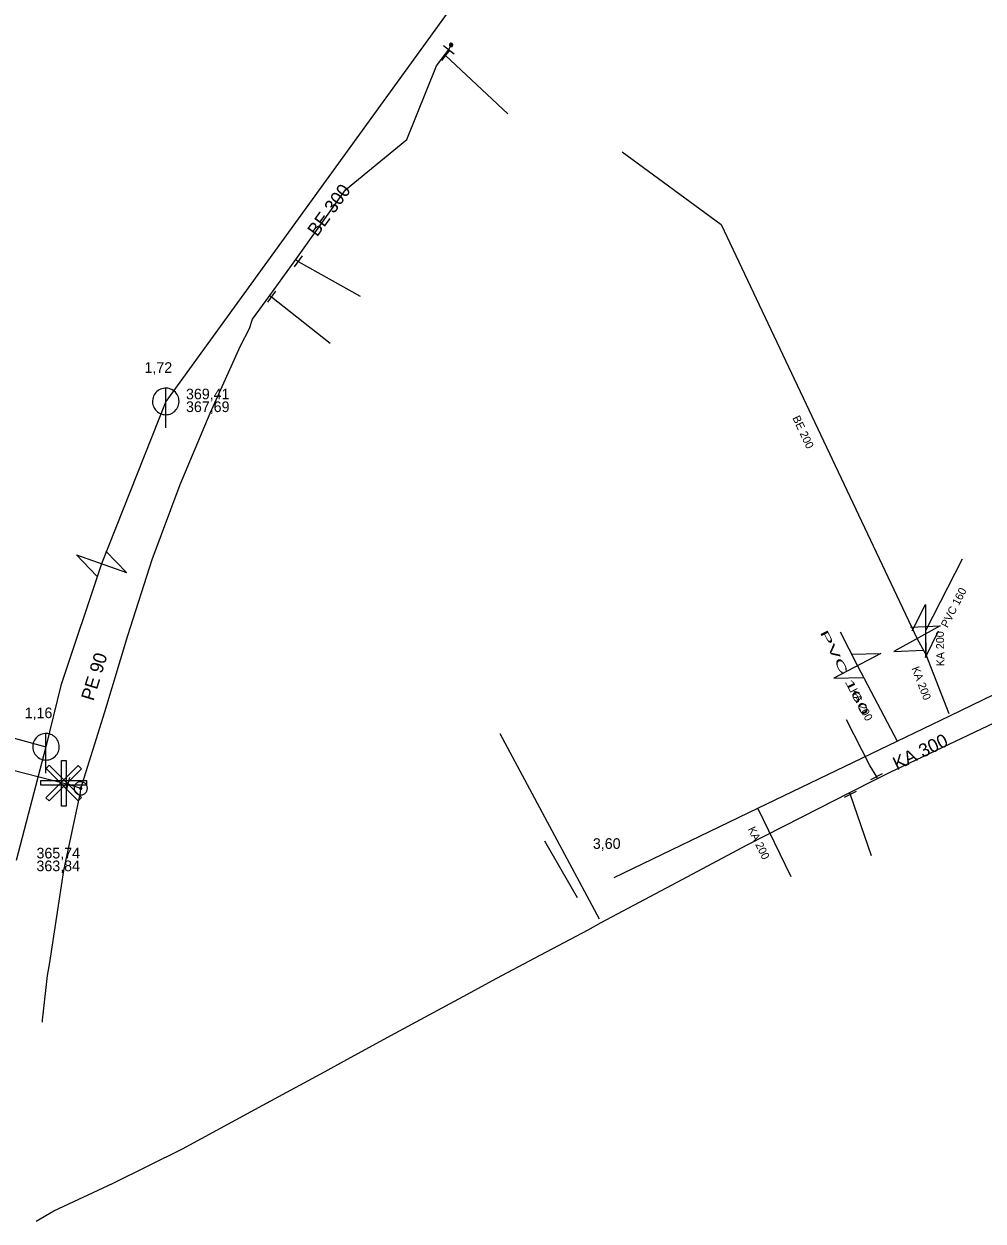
# Model space of a CAD drawing. Extents: x -809028 to -807737, y -990545 to -989489.
# Drawn here: x -808817.2 to -808745.1, y -990286.3 to -990196.1 of the extents above; entities that cross this region are included whole.
import ezdxf

# ---------------------------------------------------------------- set-up
doc = ezdxf.new("R2010")
doc.units = 0
doc.header["$LTSCALE"] = 0.32
for name, color, linetype, lineweight in [('1', 7, 'Continuous', 13), ('11', 7, 'Continuous', 13), ('12', 7, 'Continuous', 13), ('13', 7, 'Continuous', 13), ('14', 7, 'Continuous', 25), ('17', 7, 'Continuous', 25), ('22', 7, 'Continuous', 13), ('31', 7, 'Continuous', 13), ('34', 7, 'Continuous', 13), ('47', 7, 'Continuous', 13), ('9', 7, 'Continuous', 13)]:
    doc.layers.add(name, color=color, linetype=linetype, lineweight=lineweight)

msp = doc.modelspace()

# ---------------------------------------------------------------- linework, layer by layer
at = {"layer": '11'}
for p, q in [((-808746.625, -990236.437), (-808749.39, -990241.84)), ((-808755.806, -990241.917), (-808754.51, -990244.469)), ((-808749.39, -990241.84), (-808749.359, -990243.6)), ((-808754.51, -990244.469), (-808751.517, -990250.136)), ((-808759.48, -990260.34), (-808761.989, -990255.184)), ((-808778.039, -990257.649), (-808775.594, -990261.896))]:
    msp.add_line(p, q, dxfattribs=at)
for points in [[(-808772.199, -990205.759), (-808764.751, -990211.239), (-808750.02, -990242.42)], [(-808750.02, -990242.42), (-808749.359, -990243.6), (-808747.626, -990248.049)]]:
    msp.add_lwpolyline(points, dxfattribs=at)
at = {"layer": '12'}
for points in [[(-808814.407, -990251.601), (-808814.056, -990251.601), (-808814.056, -990255.036), (-808814.407, -990255.036)], [(-808813.141, -990251.965), (-808812.892, -990252.213), (-808815.321, -990254.642), (-808815.568, -990254.394)], [(-808815.559, -990252.204), (-808815.313, -990251.956), (-808812.884, -990254.385), (-808813.13, -990254.633)], [(-808812.522, -990253.11), (-808812.522, -990253.46), (-808815.958, -990253.46), (-808815.958, -990253.11)]]:
    msp.add_lwpolyline(points, close=True, dxfattribs=at)
at = {"layer": '13'}
for p, q in [((-808785.51, -990198.5), (-808780.806, -990202.892)), ((-808796.59, -990214.01), (-808791.921, -990216.627)), ((-808798.59, -990216.67), (-808794.182, -990220.164)), ((-808773.92, -990263.539), (-808781.377, -990249.592)), ((-808755.05, -990254.149), (-808753.458, -990258.738))]:
    msp.add_line(p, q, dxfattribs=at)
msp.add_lwpolyline([(-808753.045, -990252.83), (-808753.567, -990251.982), (-808755.331, -990248.533)], dxfattribs=at)
at = {"layer": '14'}
for p, q in [((-808783.475, -990192.677), (-808806.55, -990224.558)), ((-808806.55, -990224.558), (-808811.393, -990236.777))]:
    msp.add_line(p, q, dxfattribs=at)
at = {"layer": '14', "lineweight": 13}
for p, q in [((-808785.25, -990198.07), (-808785.079, -990197.719)), ((-808785.555, -990198.465), (-808785.51, -990198.5)), ((-808796.771, -990213.877), (-808796.59, -990214.01)), ((-808798.728, -990216.57), (-808798.59, -990216.67)), ((-808752.991, -990252.945), (-808753.059, -990252.809)), ((-808755.116, -990254.02), (-808755.05, -990254.149))]:
    msp.add_line(p, q, dxfattribs=at)
at = {"layer": '14'}
for points in [[(-808872.221, -990237.915), (-808866.264, -990236.723), (-808835.816, -990244.988), (-808815.565, -990250.559), (-808817.8, -990259.127)], [(-808811.393, -990236.777), (-808814.447, -990245.94), (-808815.565, -990250.559)], [(-808772.809, -990260.399), (-808761.989, -990255.184), (-808751.517, -990250.136), (-808747.555, -990248.226), (-808742.537, -990245.807), (-808731.232, -990240.357), (-808726.57, -990238.109)]]:
    msp.add_lwpolyline(points, dxfattribs=at)
at = {"layer": '17'}
for p in [(-808837.921, -990247.3), (-808812.949, -990253.69)]:
    msp.add_line(p, (-808813.92, -990253.37), dxfattribs=at)
for points in [[(-808812.949, -990253.69), (-808811.14, -990247.92), (-808809.41, -990242.19), (-808807.579, -990236.469), (-808805.461, -990230.802), (-808803.21, -990225.44), (-808800.92, -990220.379), (-808800.25, -990219.07), (-808800.03, -990218.36), (-808798.728, -990216.57), (-808796.771, -990213.877), (-808793.03, -990208.62), (-808788.399, -990204.84), (-808786.19, -990199.289), (-808785.555, -990198.465), (-808785.25, -990198.07)], [(-808816.309, -990286.27), (-808814.98, -990285.51), (-808810.51, -990283.42), (-808805.3, -990280.84), (-808799.84, -990277.87), (-808797.447, -990276.572), (-808794.55, -990275), (-808792.921, -990274.113), (-808789.28, -990272.129), (-808784.177, -990269.35), (-808781.633, -990267.989), (-808778.813, -990266.48), (-808774.763, -990264.332), (-808773.782, -990263.798), (-808768.079, -990260.75), (-808762.76, -990257.92), (-808757.39, -990255.17), (-808755.116, -990254.02), (-808752.991, -990252.945), (-808752.03, -990252.46), (-808741.73, -990247.582)], [(-808815.829, -990271.3), (-808815.829, -990271.109), (-808815.789, -990270.91), (-808815.449, -990267.77), (-808815.27, -990266.8), (-808814.21, -990259.879), (-808812.96, -990254), (-808812.949, -990253.69)]]:
    msp.add_lwpolyline(points, dxfattribs=at)
at = {"layer": '22'}
for p, q in [((-808806.55, -990226.558), (-808806.549, -990223.558)), ((-808815.565, -990252.559), (-808815.564, -990249.559))]:
    msp.add_line(p, q, dxfattribs=at)
for points in [[(-808805.55, -990224.558), (-808805.555, -990224.449), (-808805.573, -990224.341), (-808805.603, -990224.235), (-808805.643, -990224.134), (-808805.695, -990224.037), (-808805.757, -990223.947), (-808805.829, -990223.864), (-808805.909, -990223.79), (-808805.997, -990223.724), (-808806.091, -990223.669), (-808806.191, -990223.624), (-808806.296, -990223.591), (-808806.403, -990223.569), (-808806.512, -990223.559), (-808806.622, -990223.561), (-808806.73, -990223.575), (-808806.837, -990223.6), (-808806.94, -990223.637), (-808807.038, -990223.686), (-808807.13, -990223.744), (-808807.216, -990223.813), (-808807.293, -990223.89), (-808807.362, -990223.976), (-808807.421, -990224.068), (-808807.469, -990224.166), (-808807.506, -990224.269), (-808807.532, -990224.376), (-808807.546, -990224.484), (-808807.549, -990224.594), (-808807.539, -990224.703), (-808807.518, -990224.81), (-808807.484, -990224.914), (-808807.44, -990225.014), (-808807.385, -990225.109), (-808807.319, -990225.197), (-808807.245, -990225.277), (-808807.162, -990225.349), (-808807.072, -990225.411), (-808806.976, -990225.463), (-808806.874, -990225.504), (-808806.769, -990225.534), (-808806.661, -990225.552), (-808806.551, -990225.558), (-808806.442, -990225.552), (-808806.334, -990225.534), (-808806.229, -990225.505), (-808806.127, -990225.464), (-808806.03, -990225.412), (-808805.94, -990225.35), (-808805.857, -990225.279), (-808805.782, -990225.199), (-808805.717, -990225.111), (-808805.661, -990225.017), (-808805.617, -990224.917), (-808805.583, -990224.813), (-808805.561, -990224.705), (-808805.551, -990224.596)], [(-808814.565, -990250.559), (-808814.57, -990250.45), (-808814.588, -990250.342), (-808814.618, -990250.236), (-808814.658, -990250.135), (-808814.71, -990250.038), (-808814.772, -990249.948), (-808814.844, -990249.865), (-808814.924, -990249.791), (-808815.012, -990249.725), (-808815.106, -990249.67), (-808815.206, -990249.625), (-808815.311, -990249.592), (-808815.418, -990249.57), (-808815.527, -990249.56), (-808815.637, -990249.562), (-808815.745, -990249.576), (-808815.852, -990249.601), (-808815.955, -990249.638), (-808816.053, -990249.687), (-808816.145, -990249.745), (-808816.231, -990249.814), (-808816.308, -990249.891), (-808816.377, -990249.977), (-808816.436, -990250.069), (-808816.484, -990250.167), (-808816.521, -990250.27), (-808816.547, -990250.377), (-808816.561, -990250.485), (-808816.564, -990250.595), (-808816.554, -990250.704), (-808816.533, -990250.811), (-808816.499, -990250.915), (-808816.455, -990251.015), (-808816.4, -990251.11), (-808816.334, -990251.198), (-808816.26, -990251.278), (-808816.177, -990251.35), (-808816.087, -990251.412), (-808815.991, -990251.464), (-808815.889, -990251.505), (-808815.784, -990251.535), (-808815.676, -990251.553), (-808815.566, -990251.559), (-808815.457, -990251.553), (-808815.349, -990251.535), (-808815.244, -990251.506), (-808815.142, -990251.465), (-808815.045, -990251.413), (-808814.955, -990251.351), (-808814.872, -990251.28), (-808814.797, -990251.2), (-808814.732, -990251.112), (-808814.676, -990251.018), (-808814.632, -990250.918), (-808814.598, -990250.814), (-808814.576, -990250.706), (-808814.566, -990250.597)]]:
    msp.add_lwpolyline(points, close=True, dxfattribs=at)
at = {"layer": '31'}
for points in [[(-808811.728, -990237.718), (-808813.276, -990236.104), (-808809.509, -990237.449), (-808811.056, -990235.835)], [(-808750.39, -990241.84), (-808749.39, -990239.84), (-808749.39, -990243.84), (-808748.39, -990241.84)], [(-808750.508, -990241.547), (-808748.274, -990241.443), (-808751.765, -990243.396), (-808749.532, -990243.293)], [(-808754.977, -990243.585), (-808752.742, -990243.535), (-808756.278, -990245.403), (-808754.043, -990245.353)]]:
    msp.add_lwpolyline(points, dxfattribs=at)
at = {"layer": '34'}
for p, q in [((-808785.646, -990197.765), (-808784.854, -990198.375)), ((-808785.208, -990198.1), (-808785.811, -990198.898)), ((-808796.295, -990213.605), (-808796.885, -990214.413)), ((-808798.297, -990216.264), (-808798.883, -990217.074)), ((-808753.504, -990253.035), (-808752.612, -990252.583)), ((-808813.797, -990252.885), (-808814.043, -990253.854)), ((-808754.604, -990253.922), (-808755.496, -990254.374))]:
    msp.add_line(p, q, dxfattribs=at)
at = {"layer": '47'}
for points in [[(-808812.932, -990253.19), (-808812.984, -990253.191), (-808813.037, -990253.197), (-808813.087, -990253.21), (-808813.137, -990253.226), (-808813.184, -990253.249), (-808813.229, -990253.276), (-808813.27, -990253.308), (-808813.309, -990253.344), (-808813.343, -990253.383), (-808813.373, -990253.426), (-808813.399, -990253.472), (-808813.418, -990253.52), (-808813.434, -990253.57), (-808813.444, -990253.621), (-808813.448, -990253.673), (-808813.447, -990253.725), (-808813.441, -990253.778), (-808813.428, -990253.829), (-808813.412, -990253.878), (-808813.389, -990253.925), (-808813.362, -990253.97), (-808813.33, -990254.012), (-808813.294, -990254.051), (-808813.255, -990254.085), (-808813.212, -990254.114), (-808813.166, -990254.14), (-808813.118, -990254.16), (-808813.068, -990254.175), (-808813.017, -990254.185), (-808812.965, -990254.189), (-808812.913, -990254.188), (-808812.86, -990254.182), (-808812.809, -990254.17), (-808812.76, -990254.153), (-808812.713, -990254.13), (-808812.668, -990254.104), (-808812.626, -990254.072), (-808812.587, -990254.036), (-808812.553, -990253.996), (-808812.524, -990253.953), (-808812.498, -990253.907), (-808812.478, -990253.86), (-808812.463, -990253.809), (-808812.453, -990253.758), (-808812.449, -990253.706), (-808812.45, -990253.654), (-808812.456, -990253.601), (-808812.468, -990253.551), (-808812.485, -990253.501), (-808812.508, -990253.454), (-808812.534, -990253.409), (-808812.566, -990253.368), (-808812.602, -990253.329), (-808812.642, -990253.295), (-808812.685, -990253.265), (-808812.731, -990253.239), (-808812.778, -990253.22), (-808812.829, -990253.204), (-808812.88, -990253.194)], [(-808812.946, -990253.608), (-808812.955, -990253.607), (-808812.963, -990253.609), (-808812.971, -990253.611), (-808812.979, -990253.613), (-808812.987, -990253.617), (-808812.994, -990253.622), (-808813.002, -990253.627), (-808813.008, -990253.633), (-808813.013, -990253.639), (-808813.018, -990253.646), (-808813.022, -990253.654), (-808813.026, -990253.662), (-808813.028, -990253.67), (-808813.03, -990253.678), (-808813.03, -990253.687), (-808813.031, -990253.696), (-808813.029, -990253.704), (-808813.027, -990253.712), (-808813.025, -990253.72), (-808813.021, -990253.728), (-808813.016, -990253.735), (-808813.011, -990253.743), (-808813.005, -990253.749), (-808812.999, -990253.755), (-808812.992, -990253.759), (-808812.984, -990253.763), (-808812.976, -990253.767), (-808812.968, -990253.769), (-808812.96, -990253.771), (-808812.951, -990253.771), (-808812.942, -990253.772), (-808812.934, -990253.77), (-808812.926, -990253.768), (-808812.918, -990253.766), (-808812.91, -990253.762), (-808812.903, -990253.758), (-808812.895, -990253.752), (-808812.889, -990253.746), (-808812.883, -990253.74), (-808812.879, -990253.733), (-808812.875, -990253.725), (-808812.871, -990253.717), (-808812.869, -990253.709), (-808812.867, -990253.701), (-808812.867, -990253.692), (-808812.866, -990253.683), (-808812.868, -990253.675), (-808812.87, -990253.667), (-808812.872, -990253.659), (-808812.876, -990253.651), (-808812.88, -990253.644), (-808812.886, -990253.636), (-808812.892, -990253.63), (-808812.898, -990253.625), (-808812.905, -990253.62), (-808812.913, -990253.616), (-808812.921, -990253.612), (-808812.929, -990253.61), (-808812.937, -990253.608)]]:
    msp.add_lwpolyline(points, close=True, dxfattribs=at)
at = {"layer": '9'}
for points in [[(-808785.205, -990197.719), (-808785.205, -990197.732), (-808785.203, -990197.745), (-808785.2, -990197.758), (-808785.195, -990197.77), (-808785.189, -990197.782), (-808785.182, -990197.793), (-808785.174, -990197.803), (-808785.164, -990197.813), (-808785.154, -990197.821), (-808785.143, -990197.828), (-808785.131, -990197.834), (-808785.119, -990197.839), (-808785.106, -990197.842), (-808785.093, -990197.844), (-808785.08, -990197.846), (-808785.067, -990197.845), (-808785.054, -990197.843), (-808785.041, -990197.84), (-808785.029, -990197.835), (-808785.017, -990197.829), (-808785.006, -990197.822), (-808784.996, -990197.814), (-808784.986, -990197.804), (-808784.978, -990197.794), (-808784.971, -990197.783), (-808784.965, -990197.771), (-808784.96, -990197.759), (-808784.957, -990197.746), (-808784.955, -990197.733), (-808784.953, -990197.72), (-808784.954, -990197.707), (-808784.956, -990197.694), (-808784.959, -990197.681), (-808784.964, -990197.669), (-808784.97, -990197.657), (-808784.977, -990197.646), (-808784.985, -990197.636), (-808784.995, -990197.626), (-808785.005, -990197.618), (-808785.016, -990197.611), (-808785.028, -990197.605), (-808785.04, -990197.6), (-808785.053, -990197.597), (-808785.066, -990197.595), (-808785.079, -990197.594), (-808785.092, -990197.594), (-808785.105, -990197.596), (-808785.118, -990197.599), (-808785.13, -990197.604), (-808785.142, -990197.61), (-808785.153, -990197.617), (-808785.163, -990197.625), (-808785.173, -990197.635), (-808785.181, -990197.645), (-808785.188, -990197.656), (-808785.194, -990197.668), (-808785.199, -990197.68), (-808785.202, -990197.693), (-808785.204, -990197.706)], [(-808785.185, -990197.719), (-808785.186, -990197.73), (-808785.184, -990197.741), (-808785.181, -990197.752), (-808785.177, -990197.762), (-808785.172, -990197.772), (-808785.166, -990197.781), (-808785.159, -990197.79), (-808785.151, -990197.798), (-808785.142, -990197.805), (-808785.133, -990197.811), (-808785.123, -990197.816), (-808785.113, -990197.82), (-808785.102, -990197.823), (-808785.091, -990197.826), (-808785.08, -990197.826), (-808785.069, -990197.826), (-808785.058, -990197.824), (-808785.047, -990197.821), (-808785.037, -990197.817), (-808785.027, -990197.812), (-808785.018, -990197.806), (-808785.009, -990197.799), (-808785.001, -990197.791), (-808784.994, -990197.782), (-808784.988, -990197.773), (-808784.983, -990197.763), (-808784.979, -990197.753), (-808784.976, -990197.742), (-808784.974, -990197.731), (-808784.973, -990197.72), (-808784.973, -990197.709), (-808784.975, -990197.698), (-808784.978, -990197.687), (-808784.982, -990197.677), (-808784.987, -990197.667), (-808784.993, -990197.658), (-808785, -990197.649), (-808785.008, -990197.641), (-808785.017, -990197.634), (-808785.026, -990197.628), (-808785.036, -990197.623), (-808785.046, -990197.619), (-808785.057, -990197.616), (-808785.068, -990197.614), (-808785.079, -990197.614), (-808785.09, -990197.613), (-808785.101, -990197.615), (-808785.112, -990197.618), (-808785.122, -990197.622), (-808785.132, -990197.627), (-808785.141, -990197.633), (-808785.15, -990197.64), (-808785.158, -990197.648), (-808785.165, -990197.657), (-808785.171, -990197.666), (-808785.176, -990197.676), (-808785.18, -990197.686), (-808785.183, -990197.697), (-808785.185, -990197.708)], [(-808785.166, -990197.719), (-808785.166, -990197.728), (-808785.165, -990197.737), (-808785.162, -990197.746), (-808785.159, -990197.754), (-808785.155, -990197.762), (-808785.15, -990197.77), (-808785.144, -990197.777), (-808785.138, -990197.783), (-808785.131, -990197.789), (-808785.123, -990197.794), (-808785.115, -990197.798), (-808785.107, -990197.801), (-808785.098, -990197.804), (-808785.089, -990197.805), (-808785.08, -990197.807), (-808785.071, -990197.806), (-808785.062, -990197.805), (-808785.053, -990197.802), (-808785.045, -990197.799), (-808785.037, -990197.795), (-808785.029, -990197.79), (-808785.022, -990197.784), (-808785.016, -990197.778), (-808785.01, -990197.771), (-808785.005, -990197.763), (-808785.001, -990197.755), (-808784.998, -990197.747), (-808784.995, -990197.738), (-808784.994, -990197.729), (-808784.992, -990197.72), (-808784.993, -990197.711), (-808784.994, -990197.702), (-808784.997, -990197.693), (-808785, -990197.685), (-808785.004, -990197.677), (-808785.009, -990197.669), (-808785.015, -990197.662), (-808785.021, -990197.656), (-808785.028, -990197.65), (-808785.036, -990197.645), (-808785.044, -990197.641), (-808785.052, -990197.638), (-808785.061, -990197.635), (-808785.07, -990197.634), (-808785.079, -990197.633), (-808785.088, -990197.633), (-808785.097, -990197.634), (-808785.106, -990197.637), (-808785.114, -990197.64), (-808785.122, -990197.644), (-808785.13, -990197.649), (-808785.137, -990197.655), (-808785.143, -990197.661), (-808785.149, -990197.668), (-808785.154, -990197.676), (-808785.158, -990197.684), (-808785.161, -990197.692), (-808785.164, -990197.701), (-808785.165, -990197.71)], [(-808785.146, -990197.719), (-808785.146, -990197.726), (-808785.145, -990197.733), (-808785.144, -990197.74), (-808785.141, -990197.746), (-808785.138, -990197.752), (-808785.134, -990197.758), (-808785.13, -990197.764), (-808785.125, -990197.769), (-808785.119, -990197.773), (-808785.113, -990197.777), (-808785.107, -990197.78), (-808785.101, -990197.783), (-808785.094, -990197.784), (-808785.087, -990197.787), (-808785.08, -990197.787), (-808785.073, -990197.787), (-808785.066, -990197.785), (-808785.059, -990197.784), (-808785.053, -990197.781), (-808785.046, -990197.778), (-808785.041, -990197.774), (-808785.035, -990197.77), (-808785.03, -990197.765), (-808785.026, -990197.759), (-808785.022, -990197.753), (-808785.019, -990197.747), (-808785.016, -990197.741), (-808785.014, -990197.734), (-808785.013, -990197.727), (-808785.012, -990197.72), (-808785.012, -990197.713), (-808785.013, -990197.706), (-808785.015, -990197.699), (-808785.018, -990197.693), (-808785.021, -990197.686), (-808785.025, -990197.681), (-808785.029, -990197.675), (-808785.034, -990197.67), (-808785.04, -990197.666), (-808785.045, -990197.662), (-808785.052, -990197.659), (-808785.058, -990197.656), (-808785.065, -990197.654), (-808785.072, -990197.653), (-808785.079, -990197.653), (-808785.086, -990197.653), (-808785.093, -990197.653), (-808785.1, -990197.655), (-808785.106, -990197.658), (-808785.112, -990197.661), (-808785.118, -990197.665), (-808785.124, -990197.669), (-808785.129, -990197.674), (-808785.133, -990197.68), (-808785.137, -990197.685), (-808785.14, -990197.692), (-808785.143, -990197.698), (-808785.144, -990197.705), (-808785.146, -990197.712)], [(-808785.126, -990197.719), (-808785.126, -990197.724), (-808785.126, -990197.729), (-808785.125, -990197.734), (-808785.123, -990197.738), (-808785.121, -990197.743), (-808785.118, -990197.747), (-808785.115, -990197.75), (-808785.111, -990197.754), (-808785.108, -990197.757), (-808785.104, -990197.76), (-808785.099, -990197.762), (-808785.095, -990197.764), (-808785.09, -990197.765), (-808785.085, -990197.767), (-808785.08, -990197.767), (-808785.075, -990197.767), (-808785.07, -990197.766), (-808785.065, -990197.765), (-808785.061, -990197.763), (-808785.056, -990197.761), (-808785.052, -990197.758), (-808785.048, -990197.755), (-808785.045, -990197.751), (-808785.042, -990197.748), (-808785.039, -990197.744), (-808785.037, -990197.739), (-808785.035, -990197.735), (-808785.034, -990197.73), (-808785.033, -990197.725), (-808785.032, -990197.72), (-808785.032, -990197.715), (-808785.033, -990197.71), (-808785.034, -990197.705), (-808785.036, -990197.701), (-808785.038, -990197.696), (-808785.041, -990197.692), (-808785.044, -990197.688), (-808785.047, -990197.685), (-808785.051, -990197.682), (-808785.055, -990197.679), (-808785.06, -990197.677), (-808785.064, -990197.675), (-808785.069, -990197.674), (-808785.074, -990197.673), (-808785.079, -990197.673), (-808785.084, -990197.673), (-808785.089, -990197.674), (-808785.094, -990197.674), (-808785.098, -990197.676), (-808785.103, -990197.678), (-808785.107, -990197.681), (-808785.11, -990197.684), (-808785.114, -990197.687), (-808785.117, -990197.691), (-808785.12, -990197.695), (-808785.122, -990197.7), (-808785.124, -990197.704), (-808785.125, -990197.709), (-808785.126, -990197.714)], [(-808785.106, -990197.719), (-808785.106, -990197.722), (-808785.107, -990197.725), (-808785.106, -990197.727), (-808785.105, -990197.73), (-808785.104, -990197.733), (-808785.102, -990197.735), (-808785.1, -990197.737), (-808785.098, -990197.739), (-808785.096, -990197.741), (-808785.094, -990197.743), (-808785.091, -990197.745), (-808785.088, -990197.746), (-808785.086, -990197.746), (-808785.083, -990197.747), (-808785.08, -990197.747), (-808785.077, -990197.747), (-808785.074, -990197.747), (-808785.071, -990197.746), (-808785.069, -990197.745), (-808785.066, -990197.744), (-808785.064, -990197.742), (-808785.061, -990197.74), (-808785.059, -990197.738), (-808785.058, -990197.736), (-808785.056, -990197.734), (-808785.055, -990197.731), (-808785.053, -990197.728), (-808785.053, -990197.726), (-808785.052, -990197.723), (-808785.051, -990197.72), (-808785.052, -990197.717), (-808785.052, -990197.714), (-808785.053, -990197.711), (-808785.054, -990197.709), (-808785.055, -990197.706), (-808785.057, -990197.704), (-808785.058, -990197.701), (-808785.06, -990197.699), (-808785.063, -990197.698), (-808785.065, -990197.696), (-808785.068, -990197.695), (-808785.07, -990197.694), (-808785.073, -990197.693), (-808785.076, -990197.693), (-808785.079, -990197.692), (-808785.082, -990197.693), (-808785.085, -990197.692), (-808785.087, -990197.694), (-808785.09, -990197.694), (-808785.093, -990197.695), (-808785.095, -990197.697), (-808785.097, -990197.698), (-808785.099, -990197.7), (-808785.101, -990197.703), (-808785.103, -990197.705), (-808785.104, -990197.708), (-808785.105, -990197.71), (-808785.106, -990197.713), (-808785.106, -990197.716)], [(-808785.087, -990197.719), (-808785.087, -990197.721), (-808785.087, -990197.721), (-808785.086, -990197.721), (-808785.086, -990197.723), (-808785.087, -990197.724), (-808785.085, -990197.724), (-808785.085, -990197.724), (-808785.085, -990197.726), (-808785.085, -990197.726), (-808785.084, -990197.727), (-808785.082, -990197.727), (-808785.082, -990197.727), (-808785.082, -990197.728), (-808785.08, -990197.728), (-808785.08, -990197.728), (-808785.079, -990197.728), (-808785.078, -990197.728), (-808785.078, -990197.727), (-808785.077, -990197.727), (-808785.075, -990197.727), (-808785.075, -990197.726), (-808785.075, -990197.726), (-808785.074, -990197.725), (-808785.074, -990197.725), (-808785.072, -990197.724), (-808785.072, -990197.723), (-808785.071, -990197.722), (-808785.071, -990197.722), (-808785.071, -990197.721), (-808785.071, -990197.72), (-808785.071, -990197.719), (-808785.071, -990197.718), (-808785.071, -990197.718), (-808785.072, -990197.717), (-808785.072, -990197.716), (-808785.073, -990197.715), (-808785.073, -990197.715), (-808785.074, -990197.714), (-808785.074, -990197.714), (-808785.075, -990197.713), (-808785.076, -990197.713), (-808785.077, -990197.712), (-808785.077, -990197.712), (-808785.078, -990197.712), (-808785.079, -990197.712), (-808785.08, -990197.712), (-808785.081, -990197.712), (-808785.081, -990197.712), (-808785.082, -990197.713), (-808785.083, -990197.712), (-808785.084, -990197.714), (-808785.084, -990197.714), (-808785.085, -990197.714), (-808785.085, -990197.714), (-808785.086, -990197.716), (-808785.086, -990197.717), (-808785.086, -990197.718), (-808785.087, -990197.718), (-808785.087, -990197.719)]]:
    msp.add_lwpolyline(points, close=True, dxfattribs=at)

# ---------------------------------------------------------------- texts
at = {"layer": '1'}
for s, height, rotation, p in [('BE 300', 1, 54, (-808795.162, -990212.212)), ('BE 200', 0.6, 295, (-808759.412, -990225.795)), ('PVC 160 ', 0.6, 63, (-808747.725, -990241.642)), ('KA 200', 0.6, 91, (-808747.953, -990244.495)), ('PE 90 ', 1, 73, (-808811.991, -990247.159)), ('KA 200', 0.6, 291, (-808750.442, -990244.651)), ('KA 200', 0.6, 298, (-808755.084, -990246.36)), ('KA 300', 1, 26, (-808751.529, -990252.346)), ('KA 200', 0.6, 296, (-808762.773, -990256.751))]:
    msp.add_text(s, height=height, rotation=rotation, dxfattribs=at).set_placement(p)
for s, p in [('1,72', (-808808.15, -990222.406)), ('1,16', (-808817.165, -990248.407)), ('3,60', (-808774.41, -990258.247))]:
    msp.add_text(s, height=0.8, dxfattribs=at).set_placement(p)
at = {"layer": '1', "width": 2.2}
msp.add_text('PVC 160 ', height=0.6, rotation=297, dxfattribs=at).set_placement((-808757.348, -990241.95))
at = {"layer": '14'}
for s, p in [('369,41', (-808805.028, -990224.398)), ('367,69', (-808805.028, -990225.358)), ('365,74', (-808816.278, -990258.967)), ('363,84', (-808816.278, -990259.927))]:
    msp.add_text(s, height=0.8, dxfattribs=at).set_placement(p)

doc.saveas('drawing.dxf')
